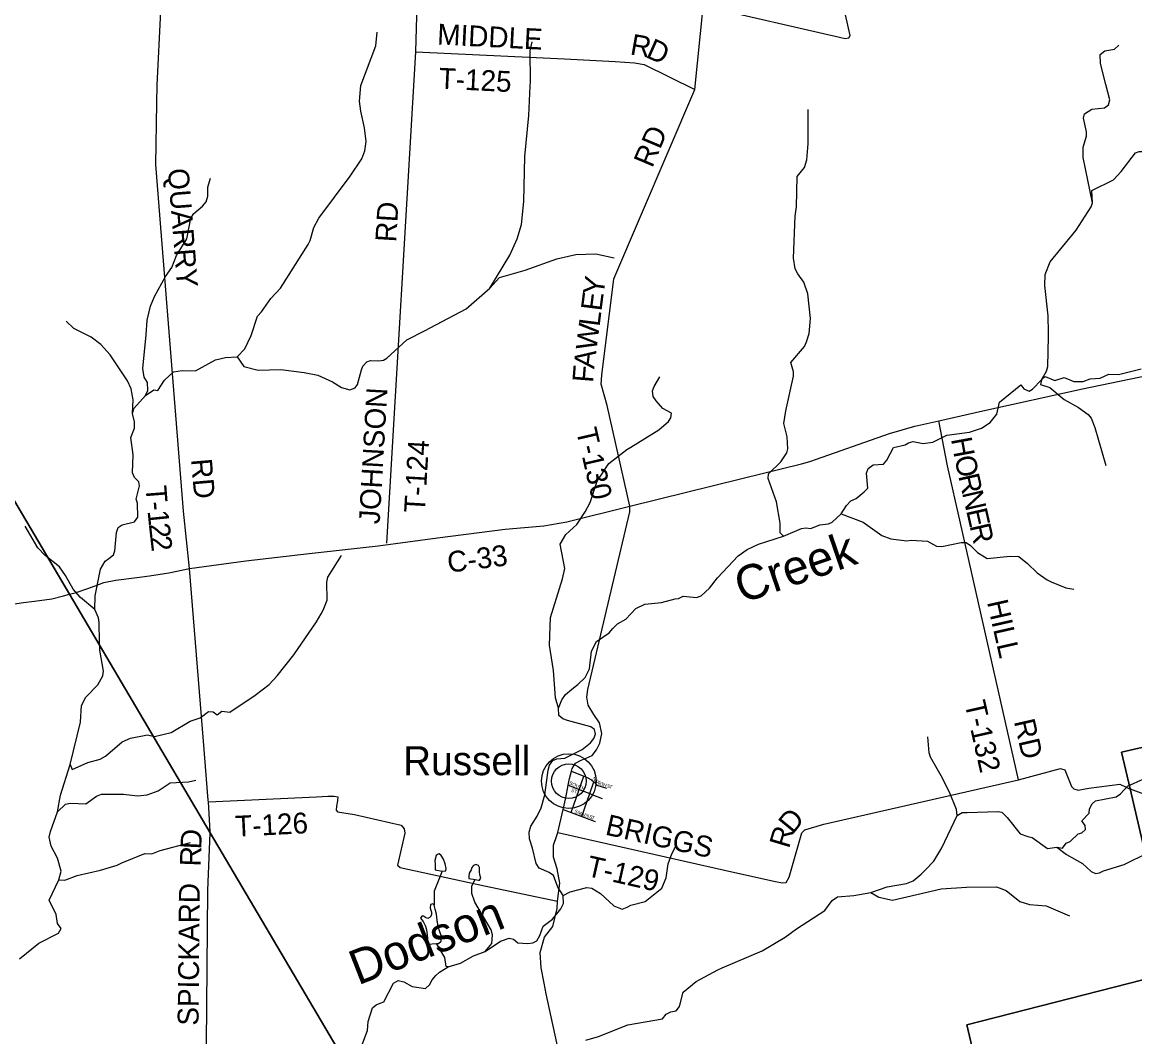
# Model space of a CAD drawing. Extents: x 1525783 to 1900577, y 218250 to 627376.
# Drawn here: x 1612574 to 1628572, y 442831 to 457419 of the extents above; entities that cross this region are included whole.
import ezdxf

# ---------------------------------------------------------------- set-up
doc = ezdxf.new("R2010")
doc.units = 0
for name, color, linetype in [('GM_X_County_Road', 7, 'Continuous'), ('GM_X_County_Road_Text', 7, 'Continuous'), ('GM_X_Minor_Lake', 7, 'Continuous'), ('GM_X_Minor_River', 7, 'Continuous'), ('GM_X_Minor_River_Text', 7, 'Continuous'), ('GM_X_Township', 7, 'Continuous'), ('GM_X_Township_Road', 7, 'Continuous'), ('GM_X_Township_Road_Text', 7, 'Continuous'), ('GM_X_Township_Subdivision', 7, 'Continuous'), ('GM_X_Township_Subdivision_Text', 7, 'Continuous'), ('GM_X_Unincorporated', 7, 'Continuous'), ('GM_X_Unincorporated_Location', 7, 'Continuous'), ('GM_X_Unincorporated_Text', 7, 'Continuous')]:
    doc.layers.add(name, color=color, linetype=linetype)

msp = doc.modelspace()

# ---------------------------------------------------------------- linework, layer by layer
at = {"layer": 'GM_X_County_Road'}
for points in [[(1621313, 450458), (1622922, 450857), (1623781, 451068), (1623901, 451105), (1625046, 451507), (1625410, 451609), (1625754, 451688), (1626388, 451832), (1627822, 452149), (1630412, 452682), (1631862, 453036), (1632829, 453273), (1633260, 453354), (1633972, 453462), (1634022, 453470)], [(1613356, 449221), (1613358, 449222), (1613363, 449223), (1613502, 449271), (1613621, 449314), (1613747, 449364), (1613918, 449396), (1614223, 449433), (1614404, 449459), (1614683, 449503), (1614981, 449564), (1615791, 449673), (1616700, 449778), (1617692, 449888), (1618545, 450003), (1619516, 450128), (1620073, 450176), (1620405, 450233), (1621313, 450458)], [(1620262, 445723), (1620276, 445766), (1620353, 446100), (1620392, 446266), (1620425, 446446), (1620443, 446545), (1620471, 446650), (1620481, 446689), (1620529, 446763), (1620610, 446807), (1620685, 446835), (1620771, 446873), (1620833, 446957), (1620878, 447050), (1620909, 447192), (1620873, 447347), (1620794, 447464), (1620710, 447601), (1620693, 447714), (1620706, 447823), (1621312, 450377), (1621313, 450458)], [(1612370, 449040), (1612591, 449075), (1612748, 449095), (1612997, 449126), (1613168, 449172), (1613251, 449193), (1613356, 449221)], [(1628486, 446402), (1628504, 446395), (1630263, 445738), (1631834, 445134), (1632382, 444921), (1632485, 444898), (1633339, 444723), (1633490, 444693), (1633765, 444611), (1634279, 444485)], [(1620080, 443603), (1620038, 443823), (1620021, 444040), (1620083, 444261), (1620202, 444414), (1620266, 444677), (1620270, 444779), (1620305, 445039), (1620268, 445243), (1620214, 445413), (1620215, 445585), (1620262, 445723)], [(1619978, 440992), (1620323, 442435), (1620310, 442524), (1620110, 443450), (1620080, 443603)]]:
    msp.add_lwpolyline(points, dxfattribs=at)
at = {"layer": 'GM_X_Minor_Lake'}
for points in [[(1618611, 445214), (1618665, 445218), (1618671, 445252), (1618654, 445318), (1618633, 445382), (1618600, 445437), (1618570, 445459), (1618554, 445458), (1618528, 445436), (1618509, 445366), (1618512, 445312), (1618511, 445232)], [(1619089, 445092), (1619137, 445081), (1619151, 445083), (1619167, 445109), (1619156, 445159), (1619150, 445207), (1619151, 445265), (1619137, 445292), (1619098, 445308), (1619063, 445293), (1619041, 445263), (1619031, 445229), (1619002, 445183), (1618994, 445141), (1618995, 445105)], [(1618511, 445232), (1618611, 445214)], [(1618995, 445105), (1619089, 445092)], [(1618532, 444172), (1618562, 444172), (1618596, 444207), (1618605, 444271), (1618578, 444340), (1618553, 444416), (1618542, 444506), (1618529, 444593), (1618514, 444667), (1618497, 444721), (1618479, 444744), (1618443, 444732), (1618438, 444678), (1618459, 444624), (1618461, 444582), (1618439, 444548), (1618406, 444530), (1618373, 444545), (1618345, 444563), (1618319, 444563), (1618301, 444538), (1618340, 444489), (1618373, 444423), (1618386, 444366), (1618397, 444298), (1618401, 444242), (1618402, 444164)], [(1618402, 444164), (1618532, 444172)]]:
    msp.add_lwpolyline(points, dxfattribs=at)
at = {"layer": 'GM_X_Minor_River'}
for points in [[(1614466, 452134), (1614525, 452123), (1614621, 452272), (1614747, 452390), (1614875, 452411), (1615066, 452408), (1615352, 452565), (1615498, 452599), (1615664, 452609), (1615774, 452723), (1615864, 452914), (1615959, 453191), (1616014, 453255), (1616150, 453447), (1616286, 453596), (1616684, 454221), (1616713, 454281), (1616769, 454469), (1616837, 454602), (1617288, 455205), (1617457, 455457), (1617502, 455572), (1617518, 455702), (1617497, 455899), (1617442, 456140), (1617422, 456284), (1617443, 456510), (1617660, 457082), (1617678, 457276)], [(1615664, 452609), (1615760, 452471), (1615967, 452418), (1616293, 452426), (1616630, 452384), (1616825, 452345), (1617034, 452246), (1617163, 452166), (1617286, 452133), (1617360, 452160), (1617397, 452211), (1617450, 452421), (1617472, 452475), (1617527, 452538), (1617583, 452557), (1617703, 452548), (1617767, 452559), (1617817, 452588), (1618106, 452851), (1618368, 452986), (1618438, 453025), (1618957, 453298), (1619299, 453596), (1619584, 454069), (1619693, 454304), (1619754, 454509), (1619786, 454839), (1619800, 455488), (1619858, 456076), (1619879, 456502), (1619882, 456566), (1619876, 457007), (1619906, 457137)], [(1620831, 448512), (1621012, 448641), (1621065, 448701), (1621136, 448770), (1621252, 448835), (1621398, 448987), (1621527, 449051), (1621765, 449074), (1621961, 449130), (1622013, 449131), (1622078, 449166), (1622269, 449146), (1622338, 449171), (1622459, 449281), (1622573, 449432), (1622868, 449747), (1622999, 449835), (1623162, 449913), (1623523, 450028), (1623778, 450139), (1623842, 450150), (1623914, 450139), (1624045, 450194), (1624169, 450204), (1624219, 450230), (1624350, 450350), (1624426, 450471), (1624491, 450538), (1624565, 450571), (1624680, 450668), (1624735, 450721), (1624713, 450934), (1624738, 451000), (1624811, 451057), (1624961, 451065), (1625007, 451122), (1625102, 451305), (1625270, 451341), (1625320, 451373), (1625386, 451392), (1625530, 451362), (1625670, 451380), (1625871, 451482), (1626197, 451525), (1626370, 451583), (1626491, 451664), (1626588, 451785), (1626626, 451958), (1626933, 452207), (1626976, 452148), (1627052, 452113), (1627102, 452142), (1627232, 452275), (1627303, 452402), (1627320, 452470), (1627330, 452902), (1627332, 452958), (1627327, 453197), (1627281, 453634), (1627285, 453794), (1627357, 453973), (1627731, 454431), (1627943, 454765), (1627964, 454820), (1627828, 455475), (1627832, 455623), (1627876, 455779), (1627877, 455843), (1627836, 456042), (1627848, 456102), (1627953, 456170), (1628139, 456190), (1628194, 456231), (1628212, 456303), (1628157, 456524), (1628081, 456824), (1628073, 456956), (1628142, 457007), (1628282, 457033), (1628342, 457088)], [(1623523, 450028), (1623474, 450077), (1623472, 450217), (1623422, 450522), (1623300, 450856), (1623303, 450924), (1623481, 451096), (1623569, 451225), (1623583, 451283), (1623576, 451459), (1623524, 451650), (1623556, 451830), (1623667, 452329), (1623666, 452394), (1623627, 452524), (1623824, 452758), (1623853, 452822), (1623892, 452943), (1623911, 453157), (1623870, 453512), (1623814, 453679), (1623726, 453803), (1623691, 453875), (1623667, 454028), (1623690, 454630), (1623708, 454766), (1623716, 455202), (1623825, 455331), (1623855, 455439), (1623873, 455613), (1623876, 455673), (1623876, 456166)], [(1627964, 454820), (1627954, 455001), (1628266, 455155), (1628377, 455274), (1628582, 455539), (1628638, 455561), (1628704, 455560), (1629017, 455528), (1629138, 455568), (1629683, 456004), (1629855, 456082), (1630124, 456130), (1630311, 456218)], [(1614476, 453475), (1614632, 453764), (1614724, 453891), (1614794, 454064), (1614941, 454304), (1614997, 454604), (1615040, 454669), (1615167, 454772), (1615220, 454837), (1615241, 454919), (1615242, 455047), (1615280, 455177)], [(1619299, 453596), (1619438, 453747), (1619805, 453856), (1620259, 454016), (1620535, 454079), (1620821, 454089), (1621086, 454029)], [(1614344, 452052), (1614382, 452122), (1614376, 452238), (1614327, 452313), (1614309, 452440), (1614354, 452924), (1614372, 453134), (1614419, 453336), (1614476, 453475)], [(1614157, 451795), (1614169, 451987), (1614142, 452146), (1614088, 452263), (1613836, 452638), (1613702, 452785), (1613566, 452890), (1613314, 453017), (1613203, 453119)], [(1627232, 452275), (1627282, 452324), (1627423, 452266), (1627558, 452311), (1627695, 452255), (1627830, 452251), (1627933, 452290), (1628075, 452300), (1628145, 452335), (1628199, 452358), (1628339, 452356), (1628664, 452434)], [(1620285, 447556), (1620243, 447704), (1620212, 448095), (1620155, 448460), (1620170, 448859), (1620343, 449417), (1620377, 449563), (1620310, 449916), (1620393, 450053), (1620547, 450196), (1620671, 450380), (1620741, 450511), (1620843, 450822), (1621008, 451073), (1621268, 451275), (1621324, 451311), (1621727, 451560), (1621865, 451678), (1621901, 451732), (1621912, 451800), (1621785, 451865), (1621691, 451977), (1621649, 452039), (1621638, 452118), (1621659, 452182), (1621741, 452319)], [(1627232, 452275), (1627215, 452211), (1627350, 452167), (1627556, 451996), (1627764, 451881), (1627904, 451777), (1627946, 451725), (1628000, 451590), (1628156, 451043)], [(1614157, 451795), (1614179, 451865), (1614344, 452052), (1614466, 452134)], [(1612536, 443949), (1612813, 444176), (1613096, 444318), (1613133, 444387), (1613083, 444460), (1613063, 444591), (1612960, 444795), (1613102, 445087), (1613132, 445213), (1613081, 445400), (1612990, 445570), (1612963, 445703), (1612978, 445781), (1613079, 446064), (1613124, 446303), (1613262, 446744), (1613413, 447352), (1613427, 447595), (1613489, 447712), (1613659, 447893), (1613733, 448020), (1613740, 448088), (1613688, 448390), (1613682, 448735), (1613681, 448789), (1613670, 448853), (1613618, 448976), (1613624, 449171), (1613697, 449556), (1613765, 449671), (1613820, 449708), (1613885, 449761), (1613906, 449819), (1613928, 450081), (1613952, 450155), (1614013, 450194), (1614190, 450233), (1614235, 450300), (1614233, 450503), (1614210, 450563), (1614261, 450755), (1614250, 450811), (1614187, 450872), (1614158, 450939), (1614167, 451199), (1614137, 451446), (1614190, 451584), (1614189, 451672), (1614157, 451795)], [(1624350, 450350), (1624668, 450228), (1624937, 450038), (1625065, 449990), (1625294, 449961), (1625358, 449972), (1625592, 449955), (1625719, 449887), (1625800, 449882), (1626075, 449937), (1626147, 449936), (1626212, 449893), (1626309, 449796), (1626449, 449706), (1626779, 449739), (1626905, 449736), (1627032, 449638), (1627168, 449502), (1627312, 449402), (1627370, 449373), (1627580, 449288), (1627694, 449265)], [(1613618, 448976), (1613411, 449146), (1613307, 449267), (1613198, 449463), (1613108, 449587), (1612901, 449751), (1612797, 449861), (1612618, 450173)], [(1614375, 447173), (1614475, 447149), (1614714, 447206), (1614989, 447369), (1615130, 447415), (1615253, 447507), (1615317, 447505), (1615376, 447462), (1615445, 447511), (1615560, 447499), (1615925, 447741), (1616123, 447894), (1616242, 448021), (1616480, 448324), (1616805, 448795), (1616873, 448914), (1616902, 448966), (1616957, 449107), (1616953, 449366), (1616966, 449437), (1617165, 449751)], [(1617441, 442665), (1617537, 442922), (1617550, 443050), (1617609, 443245), (1617661, 443288), (1617721, 443312), (1617774, 443335), (1617911, 443600), (1617981, 443641), (1618059, 443618), (1618182, 443552), (1618371, 443523), (1618432, 443575), (1618467, 443648), (1618520, 443710), (1618574, 443761), (1618701, 443836), (1618875, 443887), (1619065, 443995), (1619233, 444057), (1619451, 444206), (1619575, 444249), (1619639, 444236), (1619700, 444183), (1619846, 444171), (1619914, 444180), (1619976, 444211), (1620019, 444289), (1620063, 444420), (1620198, 444523), (1620320, 444671), (1620355, 444749), (1620354, 444863), (1620274, 444984), (1620214, 445149), (1620153, 445194), (1620008, 445254), (1619963, 445323), (1619910, 445542), (1619869, 445679), (1619865, 445773), (1619888, 445859), (1619977, 446002), (1620037, 446121), (1620087, 446307), (1620125, 446592), (1620138, 446664), (1620155, 446738), (1620204, 446804), (1620260, 446827), (1620376, 446837), (1620625, 446960), (1620744, 447057), (1620793, 447120), (1620816, 447184), (1620805, 447250), (1620749, 447289), (1620413, 447376), (1620347, 447401), (1620288, 447449), (1620285, 447556), (1620335, 447677), (1620388, 447752), (1620503, 447849), (1620563, 447896), (1620668, 447995), (1620732, 448122), (1620759, 448376), (1620831, 448512)], [(1613262, 446744), (1613292, 446673), (1613515, 446773), (1613694, 446820), (1613769, 446867), (1614011, 447073), (1614132, 447123), (1614375, 447173)], [(1626018, 446013), (1626009, 446097), (1625907, 446347), (1625790, 446584), (1625635, 446849), (1625618, 446915), (1625595, 447142)], [(1614368, 446311), (1614529, 446365), (1614702, 446481), (1614966, 446498), (1615068, 446521)], [(1627452, 445559), (1627534, 445544), (1627587, 445614), (1627645, 445637), (1627758, 445750), (1627809, 445761), (1627863, 445812), (1627858, 445867), (1627811, 445937), (1627918, 446046), (1627921, 446110), (1627958, 446180), (1628010, 446221), (1628307, 446283), (1628369, 446326), (1628466, 446433), (1628701, 446538)], [(1613079, 446064), (1613197, 446174), (1613270, 446189), (1613490, 446181), (1613640, 446292), (1613713, 446317), (1614031, 446319), (1614231, 446294), (1614368, 446311)], [(1620679, 442780), (1620859, 442836), (1621283, 443003), (1621782, 443088), (1621836, 443154), (1621903, 443191), (1621977, 443202), (1622024, 443267), (1622080, 443471), (1622264, 443623), (1622576, 443793), (1622640, 443822), (1623216, 444067), (1623547, 444263), (1623706, 444383), (1624113, 444646), (1624219, 444789), (1624297, 444842), (1624531, 444861), (1624777, 444907), (1625012, 444986), (1625292, 445033), (1625385, 445072), (1625502, 445170), (1625560, 445228), (1625684, 445356), (1625796, 445547), (1626018, 446013), (1626089, 446054), (1626160, 446057), (1626602, 446071), (1626662, 446058), (1626737, 445985), (1626924, 445747), (1627035, 445711), (1627099, 445696), (1627316, 445537), (1627452, 445559), (1627593, 445451), (1627819, 445320), (1627947, 445205), (1628007, 445176), (1628063, 445187), (1628123, 445216), (1628418, 445307), (1628768, 445478)], [(1614337, 445464), (1614435, 445459), (1614556, 445508), (1614991, 445624)], [(1620354, 444863), (1620453, 444914), (1620695, 444975), (1620763, 444966), (1620888, 444890), (1621081, 444714), (1621203, 444666), (1621271, 444693), (1621325, 444724), (1621534, 444776), (1621772, 444967), (1621834, 445118), (1621864, 445316), (1621914, 445462), (1621980, 445589)], [(1613102, 445087), (1613188, 445080), (1613363, 445149), (1613699, 445227), (1613941, 445297), (1614008, 445330), (1614337, 445464)], [(1618611, 445214), (1618495, 444924), (1618497, 444721)], [(1619233, 444057), (1619329, 444172), (1619338, 444298), (1619319, 444368), (1619081, 444764), (1619040, 444892), (1619040, 444999), (1619089, 445092)], [(1624777, 444907), (1624890, 444838), (1625089, 444795), (1625787, 444956), (1626151, 444984), (1626582, 444988), (1626725, 444936), (1626919, 444775), (1627058, 444734), (1627300, 444712), (1627635, 444570)], [(1618701, 443836), (1618669, 443842), (1618653, 443970), (1618532, 444172)]]:
    msp.add_lwpolyline(points, dxfattribs=at)
at = {"layer": 'GM_X_Township'}
for points in [[(1608973, 456441), (1613251, 449193), (1615276, 445762), (1618069, 441028), (1618764, 439851), (1615012, 437595), (1611723, 435618)], [(1632446, 447856), (1628381, 446924), (1628504, 446395), (1629120, 443761), (1626156, 443002), (1626649, 440908), (1626934, 439694), (1626936, 439077), (1623692, 439720), (1619861, 440479), (1619822, 440487), (1618764, 439851), (1618069, 441028), (1615276, 445762), (1613251, 449193), (1608973, 456441)], [(1627134, 430332), (1627027, 435051), (1626936, 439077), (1626934, 439694), (1626649, 440908), (1626156, 443002), (1629120, 443761), (1628504, 446395), (1628381, 446924), (1632446, 447856)]]:
    msp.add_lwpolyline(points, dxfattribs=at)
at = {"layer": 'GM_X_Township_Road'}
for points in [[(1617815, 449927), (1618232, 456993), (1618232, 456999), (1618252, 457669), (1618474, 460787)], [(1614509, 456256), (1614509, 456258), (1614512, 456513), (1614569, 457580), (1614670, 459174), (1614377, 459716)], [(1621313, 450458), (1620985, 451909), (1620897, 452216), (1620907, 452345), (1621082, 453728), (1622245, 456450), (1622365, 457634), (1622405, 457643), (1624328, 457204), (1624406, 457184), (1624462, 457194), (1624479, 457230), (1624304, 458019), (1624327, 458062), (1624388, 458091), (1627063, 458711)], [(1618232, 456993), (1620372, 456893), (1621099, 456854), (1621379, 456834), (1621517, 456810), (1622245, 456450)], [(1614981, 449564), (1614894, 450389), (1614568, 454466), (1614496, 455374), (1614509, 456256)], [(1626065, 450217), (1626064, 450218), (1625879, 451039), (1625754, 451688)], [(1626898, 446523), (1626065, 450217)], [(1615248, 446232), (1615179, 447081), (1614981, 449564)], [(1620276, 445766), (1622821, 445192), (1623407, 445061), (1623506, 445045), (1623561, 445051), (1623603, 445126), (1623786, 445761), (1623829, 445808), (1624102, 445886), (1626898, 446523), (1627505, 446687), (1627567, 446669), (1627663, 446427), (1627694, 446398), (1627758, 446377), (1627911, 446404), (1628360, 446464), (1628437, 446424), (1628486, 446402)], [(1615950, 441040), (1615269, 441946), (1615219, 442056), (1615217, 442177), (1615242, 444936), (1615276, 445762), (1615277, 445781), (1615250, 446209), (1615248, 446230), (1615248, 446232)], [(1615250, 446209), (1616803, 446281), (1616970, 446289), (1617058, 446288), (1617110, 446279), (1617107, 446225), (1617093, 446147), (1617087, 446091), (1617106, 446066), (1617352, 446025), (1618021, 445872), (1618066, 445822), (1618075, 445756), (1617970, 445298), (1618007, 445264), (1619223, 445001), (1620064, 444823)], [(1620064, 444823), (1620064, 444823), (1620270, 444779)]]:
    msp.add_lwpolyline(points, dxfattribs=at)
at = {"layer": 'GM_X_Township_Subdivision'}
for points in [[(1620468, 446057), (1620583, 446385), (1620651, 446577)], [(1620471, 446650), (1620651, 446577), (1620697, 446558), (1620762, 446523), (1620794, 446495), (1620797, 446493)], [(1620425, 446446), (1620583, 446385), (1620735, 446327), (1620766, 446315), (1620766, 446315)], [(1620619, 446000), (1620735, 446327), (1620794, 446495)], [(1620797, 446493), (1620805, 446486), (1620839, 446447), (1620978, 446403)], [(1620766, 446315), (1620913, 446258)], [(1620353, 446100), (1620468, 446057), (1620619, 446000), (1620815, 445926)]]:
    msp.add_lwpolyline(points, dxfattribs=at)
at = {"layer": 'GM_X_Unincorporated'}
for radius in [393, 249]:
    msp.add_circle((1620434, 446507), radius, dxfattribs=at)
at = {"layer": 'GM_X_Unincorporated_Location'}
msp.add_line((1620434, 446507), (1620434, 446507), dxfattribs=at)

# ---------------------------------------------------------------- texts
at = {"layer": 'GM_X_County_Road_Text'}
msp.add_text('C-33', height=300, rotation=7.2099, dxfattribs=at).set_placement((1618705, 449502))
at = {"layer": 'GM_X_Minor_River_Text'}
for s, rotation, p in [('Creek', 18.9586, (1622924, 449058)), ('Dodson', 21.3922, (1617402, 443567))]:
    msp.add_text(s, height=500, rotation=rotation, dxfattribs=at).set_placement(p)
at = {"layer": 'GM_X_Township_Road_Text'}
for s, rotation, p in [('MIDDLE', 357.1731, (1618536, 457099)), ('R', 350.068, (1621304, 456958)), ('D', 335.9617, (1621528, 456921)), ('T-125', 357.1941, (1618557, 456465)), ('RD', 67.1899, (1621633, 455314)), ('QUARRY', 274.5609, (1614666, 455308)), ('RD', 86.5168, (1617950, 454251)), ('Y', 81.9284, (1620931, 453479)), ('E', 82.7618, (1620903, 453257)), ('L', 82.7639, (1620875, 453034)), ('W', 82.7624, (1620831, 452690)), ('A', 83.0028, (1620799, 452428)), ('F', 85.5102, (1620783, 452230)), ('JOHNSON', 86.6867, (1617713, 450198)), ('T-130', 283.0157, (1620535, 451552)), ('T-124', 86.6338, (1618363, 450358)), ('H', 280.4319, (1625928, 451426)), ('O', 281.792, (1625978, 451159)), ('RD', 274.9272, (1615000, 451133)), ('R', 282.8014, (1626033, 450895)), ('T', 274.5302, (1614346, 450745)), ('N', 282.881, (1626087, 450654)), ('1', 275.6544, (1614375, 450392)), ('-', 275.0706, (1614364, 450518)), ('E', 282.8814, (1626146, 450397)), ('2', 276.2632, (1614393, 450204)), ('R', 282.8804, (1626196, 450178)), ('2', 276.4888, (1614414, 450019)), ('HILL', 282.7155, (1626446, 449082)), ('T-132', 282.742, (1626123, 447630)), ('RD', 282.9568, (1626833, 447366)), ('T-126', 2.807, (1615643, 445707)), ('D', 50.5326, (1623655, 445736)), ('BRIGGS', 347.3702, (1620945, 445739)), ('D', 87.3617, (1615147, 445522)), ('R', 73.4099, (1623599, 445527)), ('R', 87.9309, (1615139, 445276)), ('T-129', 347.2586, (1620672, 445147)), ('SPICKARD', 89.4435, (1615108, 442989))]:
    msp.add_text(s, height=300, rotation=rotation, dxfattribs=at).set_placement(p)
at = {"layer": 'GM_X_Township_Subdivision_Text'}
for s, rotation, p in [('N', 318.0924, (1620767, 446533)), ('O', 315.17, (1620799, 446504)), ('SOUTH', 338.4312, (1620434, 446460)), ('ST', 338.1961, (1620460, 446358)), ('R', 333.7968, (1620845, 446463)), ('T', 343.3172, (1620889, 446442)), ('H', 343.4101, (1620922, 446432)), ('S', 343.4316, (1620977, 446416)), ('T', 343.4054, (1621011, 446406)), ('S', 337.1332, (1620509, 446055)), ('M', 337.1251, (1620554, 446036)), ('A', 339.4068, (1620605, 446015)), ('I', 341.415, (1620648, 445999)), ('N', 341.5715, (1620669, 445992)), ('S', 341.5694, (1620723, 445974)), ('T', 341.5694, (1620756, 445962))]:
    msp.add_text(s, height=50, rotation=rotation, dxfattribs=at).set_placement(p)
at = {"layer": 'GM_X_Unincorporated_Text'}
msp.add_text('Russell', height=417, rotation=0, dxfattribs=at).set_placement((1618050, 446592))

doc.saveas('drawing.dxf')
